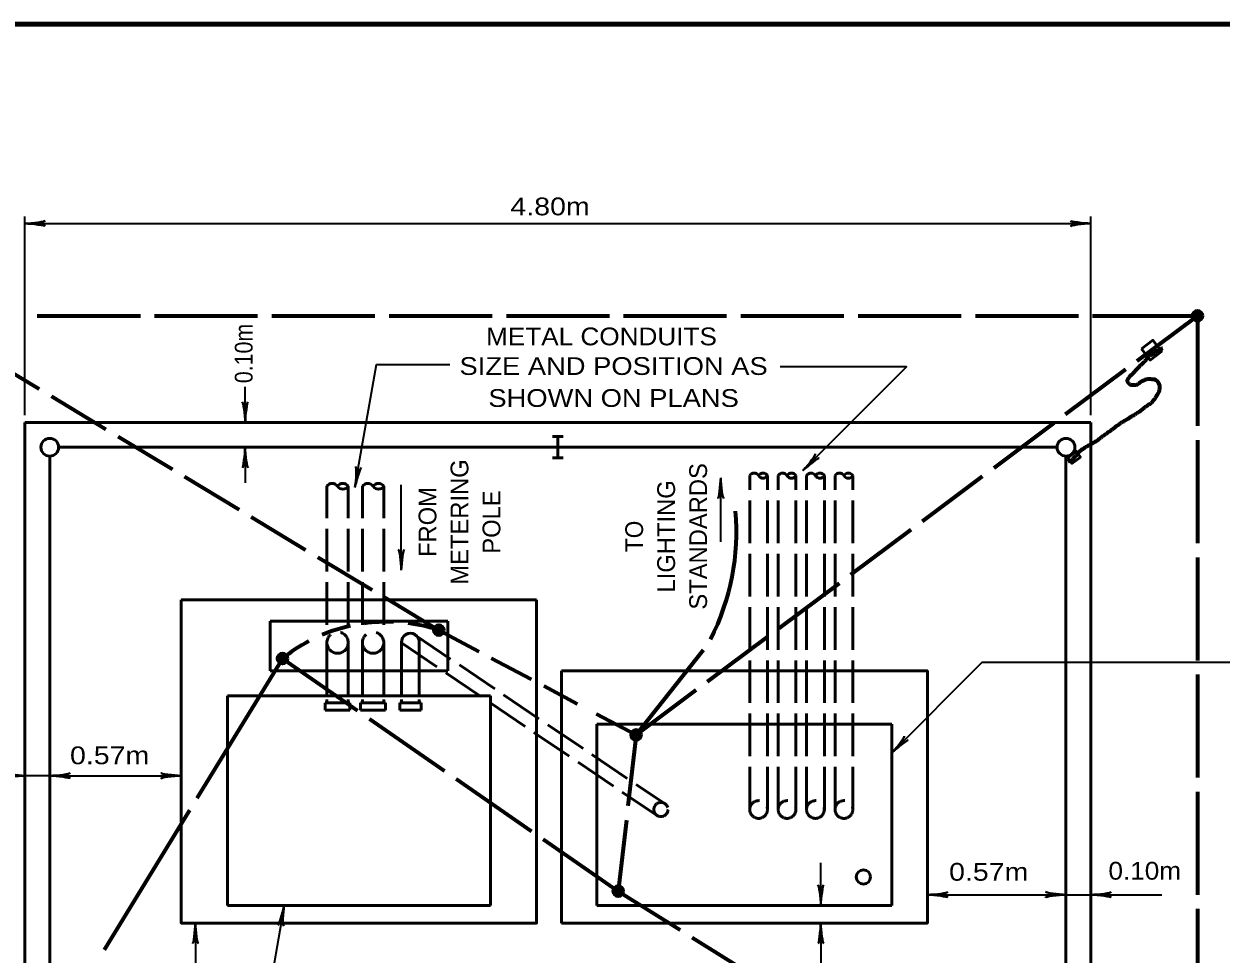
# Model space of a CAD drawing. Extents: x -30 to 826, y -11 to 533.
# Drawn here: x 133.1 to 335.3, y 369.9 to 527 of the extents above; entities that cross this region are included whole.
import ezdxf
from ezdxf.enums import TextEntityAlignment as Align

# ---------------------------------------------------------------- set-up
doc = ezdxf.new("R2010")
doc.units = 0
doc.header["$LTSCALE"] = 1.2
doc.linetypes.add('LONG_DASHED', pattern=[7.5, 6, -1.5])
doc.layers.add('1', color=7, linetype='Continuous', lineweight=53)

msp = doc.modelspace()

# ---------------------------------------------------------------- hatches: boundary and pattern name
at = {"layer": '1'}
for points in [[(332.199, 477.732, 1), (330.399, 477.732, 1)], [(204.099, 424.632, 1), (202.299, 424.632, 1)], [(177.699, 419.832, 1), (175.899, 419.832, 1)], [(237.399, 406.932, 1), (235.599, 406.932, 1)], [(234.399, 380.532, 1), (232.599, 380.532, 1)]]:
    msp.add_hatch(color=256, dxfattribs=at).paths.add_polyline_path(points)

# ---------------------------------------------------------------- linework, layer by layer
at = {"layer": '1', "lineweight": 35}
for p, q in [((133.299, 460.932), (133.299, 494.532)), ((133.299, 493.332), (313.299, 493.332)), ((313.299, 460.932), (313.299, 494.532)), ((170.499, 459.732), (170.499, 465.732)), ((170.499, 455.532), (170.499, 449.532)), ((196.859, 434.795), (196.859, 449.195)), ((250.808, 439.55), (250.808, 450.35)), ((133.299, 400.032), (121.299, 400.032)), ((137.499, 400.032), (133.299, 400.032)), ((137.499, 400.032), (159.699, 400.032)), ((267.699, 378.132), (267.699, 385.332)), ((162.099, 375.132), (162.099, 344.532)), ((267.699, 375.132), (267.699, 364.332))]:
    msp.add_line(p, q, dxfattribs=at)
at = {"layer": '1', "lineweight": 70}
for p, q in [((135.399, 477.732), (152.799, 477.732)), ((155.199, 477.732), (172.599, 477.732)), ((174.999, 477.732), (192.399, 477.732)), ((194.799, 477.732), (212.199, 477.732)), ((214.599, 477.732), (231.999, 477.732)), ((234.399, 477.732), (251.799, 477.732)), ((254.199, 477.732), (271.599, 477.732)), ((273.999, 477.732), (291.399, 477.732)), ((293.799, 477.732), (311.199, 477.732)), ((313.599, 477.732), (331.299, 477.732)), ((321.131, 470.139), (331.299, 477.732)), ((331.299, 477.732), (331.299, 459.132)), ((126.543, 470.94), (135.733, 465.388)), ((309.041, 461.109), (319.208, 468.703)), ((137.787, 464.147), (146.977, 458.595)), ((296.951, 452.08), (307.118, 459.673)), ((149.031, 457.354), (158.222, 451.803)), ((331.299, 456.732), (331.299, 439.332)), ((160.276, 450.562), (169.466, 445.01)), ((284.86, 443.05), (295.028, 450.644)), ((171.52, 443.769), (180.71, 438.218)), ((272.77, 434.021), (282.937, 441.614)), ((182.764, 436.977), (191.954, 431.425)), ((331.299, 436.932), (331.299, 419.532)), ((260.68, 424.991), (270.847, 432.585)), ((194.009, 430.184), (203.199, 424.632)), ((203.199, 424.632), (209.934, 421.052)), ((248.589, 415.962), (258.757, 423.555)), ((236.499, 406.932), (247.899, 421.332)), ((176.799, 419.832), (162.363, 396.243)), ((176.799, 419.832), (189.494, 411.033)), ((212.054, 419.926), (218.789, 416.346)), ((331.299, 417.132), (331.299, 399.732)), ((220.908, 415.219), (226.584, 412.202)), ((236.499, 406.932), (246.666, 414.526)), ((229.763, 410.512), (236.499, 406.932)), ((191.467, 409.665), (204.163, 400.866)), ((236.499, 406.932), (235.134, 394.925)), ((206.135, 399.499), (218.831, 390.699)), ((331.299, 397.332), (331.299, 379.932)), ((161.111, 394.196), (146.675, 370.606)), ((234.863, 392.54), (233.499, 380.532)), ((220.803, 389.332), (233.499, 380.532)), ((233.499, 380.532), (243.944, 373.996)), ((331.299, 377.532), (331.299, 360.132)), ((245.978, 372.723), (256.423, 366.187))]:
    msp.add_line(p, q, dxfattribs=at)
at = {"layer": '1'}
for p, q in [((133.299, 459.732), (313.299, 459.732)), ((133.299, 459.732), (133.299, 338.532)), ((313.299, 459.732), (313.299, 338.532)), ((222.399, 457.332), (224.199, 457.332)), ((223.299, 457.332), (223.299, 453.732)), ((138.999, 455.532), (307.599, 455.532)), ((137.499, 454.032), (137.499, 346.032)), ((222.399, 453.732), (224.199, 453.732)), ((309.099, 454.032), (309.099, 346.032)), ((159.699, 429.732), (219.699, 429.732)), ((174.699, 426.132), (204.699, 426.132)), ((174.699, 426.132), (174.699, 417.732)), ((204.699, 417.732), (204.699, 426.132)), ((184.299, 422.532), (184.299, 413.532)), ((187.899, 422.532), (187.899, 413.532)), ((190.299, 422.532), (190.299, 413.532)), ((193.899, 422.532), (193.899, 413.532)), ((196.899, 422.532), (196.899, 413.532)), ((199.899, 422.532), (199.899, 413.532)), ((174.699, 417.732), (204.699, 417.732)), ((223.899, 375.132), (223.899, 417.732)), ((167.499, 413.532), (211.899, 413.532)), ((167.499, 413.532), (167.499, 378.132)), ((184.299, 412.932), (184.299, 412.332)), ((187.899, 412.932), (187.899, 412.332)), ((190.299, 412.932), (190.299, 412.332)), ((193.899, 412.932), (193.899, 412.332)), ((196.899, 412.932), (196.899, 412.332)), ((199.899, 412.932), (199.899, 412.332)), ((211.899, 378.132), (211.899, 413.532)), ((279.699, 408.732), (229.899, 408.732)), ((229.899, 378.132), (229.899, 408.732)), ((279.699, 378.132), (279.699, 408.732)), ((167.499, 378.132), (211.899, 378.132)), ((229.899, 378.132), (279.699, 378.132))]:
    msp.add_line(p, q, dxfattribs=at)
at = {"layer": '1', "linetype": 'LONG_DASHED'}
for p, q in [((184.299, 425.532), (184.299, 448.932)), ((187.899, 425.532), (187.899, 448.932)), ((190.299, 425.532), (190.299, 448.932)), ((193.899, 425.532), (193.899, 448.932)), ((255.699, 394.332), (255.699, 450.732)), ((258.699, 394.332), (258.699, 450.732)), ((260.499, 394.332), (260.499, 450.732)), ((263.499, 394.332), (263.499, 450.732)), ((265.299, 394.332), (265.299, 450.732)), ((268.299, 394.332), (268.299, 450.732)), ((270.099, 394.332), (270.099, 450.732)), ((273.099, 394.332), (273.099, 450.732)), ((196.899, 422.48), (240.299, 393.139)), ((199.216, 423.786), (241.632, 395.111)), ((183.999, 412.332), (188.199, 412.332)), ((183.999, 412.332), (183.999, 411.132)), ((183.999, 411.132), (188.199, 411.132)), ((188.199, 412.332), (188.199, 411.132)), ((189.999, 412.332), (194.199, 412.332)), ((189.999, 412.332), (189.999, 411.132)), ((189.999, 411.132), (194.199, 411.132)), ((194.199, 412.332), (194.199, 411.132)), ((196.599, 412.332), (200.199, 412.332)), ((196.599, 412.332), (196.599, 411.132)), ((196.599, 411.132), (200.199, 411.132)), ((200.199, 412.332), (200.199, 411.132))]:
    msp.add_line(p, q, dxfattribs=at)
at = {"layer": '1', "lineweight": 158}
msp.add_lwpolyline([(819.196, 527.044), (27.496, 526.944), (27.596, 0.944)], dxfattribs=at)
at = {"layer": '1'}
for points in [[(321.855, 472.177), (323.778, 473.613), (325.214, 471.69), (323.292, 470.254)], [(309.385, 453.753), (310.827, 454.83), (311.545, 453.868), (310.103, 452.791), (309.385, 453.753)]]:
    msp.add_lwpolyline(points, close=True, dxfattribs=at)
at = {"layer": '1', "lineweight": 35}
for points in [[(189.031, 448.766), (192.694, 469.537), (205.038, 469.537)], [(264.675, 451.599), (282.189, 469.113), (260.81, 469.113)], [(279.699, 403.932), (294.972, 419.206), (340.444, 419.206)], [(177.099, 378.132), (175.149, 367.075), (179.094, 367.075)], [(285.699, 379.932), (309.099, 379.932), (313.299, 379.932), (325.299, 379.932)]]:
    msp.add_lwpolyline(points, dxfattribs=at)
at = {"layer": '1'}
for points in [[(159.699, 429.732), (159.699, 375.132), (219.699, 375.132), (219.699, 429.732)], [(223.899, 375.132), (285.699, 375.132), (285.699, 417.732), (223.899, 417.732)]]:
    msp.add_lwpolyline(points, dxfattribs=at)
for centre, radius in [((331.299, 477.732), 0.9), ((137.499, 455.532), 1.5), ((309.099, 455.532), 1.5), ((203.199, 424.632), 0.9), ((176.799, 419.832), 0.9), ((236.499, 406.932), 0.9), ((274.899, 382.932), 1.2), ((233.499, 380.532), 0.9)]:
    msp.add_circle(centre, radius, dxfattribs=at)
at = {"layer": '1', "linetype": 'LONG_DASHED'}
for centre, radius in [((186.099, 422.532), 1.8), ((192.099, 422.532), 1.8), ((240.699, 394.332), 1.2), ((257.199, 394.332), 1.5), ((261.999, 394.332), 1.5), ((266.799, 394.332), 1.5), ((271.599, 394.332), 1.5)]:
    msp.add_circle(centre, radius, dxfattribs=at)
at = {"layer": '1'}
for centre, radius, start, end in [((256.449, 450.307), 0.862, 29.57629, 150.42371), ((257.949, 450.307), 0.862, 29.57629, 150.42371), ((261.249, 450.307), 0.862, 29.57629, 150.42371), ((262.749, 450.307), 0.862, 29.57629, 150.42371), ((266.049, 450.307), 0.862, 29.57629, 150.42371), ((267.549, 450.307), 0.862, 29.57629, 150.42371), ((270.849, 450.307), 0.862, 29.57629, 150.42371), ((272.349, 450.307), 0.862, 29.57629, 150.42371), ((185.199, 448.345), 1.075, 33.11864, 146.88135), ((186.999, 448.345), 1.075, 33.11864, 146.88135), ((186.999, 449.519), 1.075, 213.11865, 326.88136), ((191.199, 448.345), 1.075, 33.11864, 146.88135), ((192.999, 448.345), 1.075, 33.11864, 146.88135), ((192.999, 449.519), 1.075, 213.11865, 326.88136), ((257.949, 451.158), 0.862, 209.57629, 330.42371), ((262.749, 451.158), 0.862, 209.57629, 330.42371), ((267.549, 451.158), 0.862, 209.57629, 330.42371), ((272.349, 451.158), 0.862, 209.57629, 330.42371), ((198.399, 422.61), 1.502, 357.01919, 182.98081)]:
    msp.add_arc(centre, radius, start, end, dxfattribs=at)
at = {"layer": '1', "lineweight": 70}
for centre, radius, start, end in [((213.771, 441.21), 39.685, 332.90084, 5.09207), ((194.421, 397.91), 28.127, 102.75016, 112.84762), ((194.421, 397.91), 28.127, 87.76241, 97.85974), ((194.421, 397.91), 28.127, 71.81547, 82.6976), ((194.421, 397.91), 28.127, 117.91242, 128.79422)]:
    msp.add_arc(centre, radius, start, end, dxfattribs=at)
at = {"layer": '1', "lineweight": 40}
for centre, major_axis, ratio, start_param, end_param in [((134.643, 493.078), (2.108, -0.211), 0.07063, 6.2823074, 8.5597026), ((134.643, 493.078), (2.108, -0.211), 0.07063, 6.2823074, 8.5597026), ((134.608, 493.664), (-2.143, -0.187), 0.122415, 0.8963533, 3.1415927), ((134.608, 493.664), (-2.143, -0.187), 0.122415, 0.8963533, 3.1415927), ((311.989, 493.001), (2.143, 0.187), 0.122415, 0.8963533, 3.1415927), ((311.954, 493.586), (-2.108, 0.211), 0.07063, 6.2823074, 8.5597026), ((170.167, 461.042), (0.187, -2.143), 0.122415, 0.8963533, 3.1415927), ((170.167, 461.042), (0.187, -2.143), 0.122415, 0.8963533, 3.1415927), ((170.753, 461.077), (0.211, 2.108), 0.07063, 6.2823074, 8.5597026), ((170.753, 461.077), (0.211, 2.108), 0.07063, 6.2823074, 8.5597026), ((170.245, 454.188), (-0.211, -2.108), 0.07063, 6.2823074, 8.5597026), ((170.83, 454.223), (-0.187, 2.143), 0.122415, 0.8963533, 3.1415927), ((265.366, 452.759), (-1.383, -1.648), 0.122415, 0.8963533, 3.1415927), ((265.805, 452.37), (1.639, 1.341), 0.07063, 6.2823074, 8.5597026), ((188.932, 450.113), (-0.188, -2.143), 0.122415, 0.8963533, 3.1415927), ((188.932, 450.113), (-0.188, -2.143), 0.122415, 0.8963533, 3.1415927), ((189.515, 450.046), (0.574, 2.039), 0.07063, 6.2823074, 8.5597026), ((189.515, 450.046), (0.574, 2.039), 0.07063, 6.2823074, 8.5597026), ((250.554, 449.005), (0.211, 2.108), 0.07063, 3.1407148, 5.41811), ((250.554, 449.005), (0.211, 2.108), 0.07063, 3.1407148, 5.41811), ((251.139, 449.041), (-0.187, 2.143), 0.122415, 0.8963533, 3.1415927), ((251.139, 449.041), (-0.187, 2.143), 0.122415, 0.8963533, 3.1415927), ((196.528, 436.104), (0.187, -2.143), 0.122415, 0.8963533, 3.1415927), ((196.528, 436.104), (0.187, -2.143), 0.122415, 0.8963533, 3.1415927), ((197.113, 436.14), (-0.211, -2.108), 0.07063, 3.1407148, 5.41811), ((197.113, 436.14), (-0.211, -2.108), 0.07063, 3.1407148, 5.41811), ((280.39, 405.093), (-1.383, -1.648), 0.122415, 0.8963533, 3.1415927), ((280.39, 405.093), (-1.383, -1.648), 0.122415, 0.8963533, 3.1415927), ((280.829, 404.704), (1.639, 1.341), 0.07063, 6.2823074, 8.5597026), ((280.829, 404.704), (1.639, 1.341), 0.07063, 6.2823074, 8.5597026), ((131.954, 400.286), (2.108, -0.211), 0.07063, 3.1407148, 5.41811), ((131.954, 400.286), (2.108, -0.211), 0.07063, 3.1407148, 5.41811), ((138.808, 400.364), (-2.143, -0.187), 0.122415, 0.8963533, 3.1415927), ((138.808, 400.364), (-2.143, -0.187), 0.122415, 0.8963533, 3.1415927), ((158.354, 400.286), (2.108, -0.211), 0.07063, 3.1407148, 5.41811), ((131.989, 399.701), (2.143, 0.187), 0.122415, 0.8963533, 3.1415927), ((131.989, 399.701), (2.143, 0.187), 0.122415, 0.8963533, 3.1415927), ((138.843, 399.778), (-2.108, 0.211), 0.07063, 3.1407148, 5.41811), ((138.843, 399.778), (-2.108, 0.211), 0.07063, 3.1407148, 5.41811), ((158.389, 399.701), (2.143, 0.187), 0.122415, 0.8963533, 3.1415927), ((267.367, 379.442), (0.187, -2.143), 0.122415, 0.8963533, 3.1415927), ((267.367, 379.442), (0.187, -2.143), 0.122415, 0.8963533, 3.1415927), ((267.953, 379.477), (-0.211, -2.108), 0.07063, 3.1407148, 5.41811), ((267.953, 379.477), (-0.211, -2.108), 0.07063, 3.1407148, 5.41811), ((287.008, 380.264), (-2.143, -0.187), 0.122415, 0.8963533, 3.1415927), ((307.754, 380.186), (2.108, -0.211), 0.07063, 3.1407148, 5.41811), ((307.754, 380.186), (2.108, -0.211), 0.07063, 3.1407148, 5.41811), ((314.608, 380.264), (-2.143, -0.187), 0.122415, 0.8963533, 3.1415927), ((176.615, 376.852), (-0.574, -2.039), 0.07063, 6.2823074, 8.5597026), ((177.198, 376.785), (0.188, 2.143), 0.122415, 0.8963533, 3.1415927), ((287.043, 379.678), (-2.108, 0.211), 0.07063, 3.1407148, 5.41811), ((307.789, 379.601), (2.143, 0.187), 0.122415, 0.8963533, 3.1415927), ((307.789, 379.601), (2.143, 0.187), 0.122415, 0.8963533, 3.1415927), ((314.643, 379.678), (-2.108, 0.211), 0.07063, 3.1407148, 5.41811), ((161.845, 373.788), (0.211, 2.108), 0.07063, 3.1407148, 5.41811), ((161.845, 373.788), (0.211, 2.108), 0.07063, 3.1407148, 5.41811), ((162.43, 373.823), (-0.187, 2.143), 0.122415, 0.8963533, 3.1415927), ((162.43, 373.823), (-0.187, 2.143), 0.122415, 0.8963533, 3.1415927), ((267.445, 373.788), (0.211, 2.108), 0.07063, 3.1407148, 5.41811), ((268.03, 373.823), (-0.187, 2.143), 0.122415, 0.8963533, 3.1415927)]:
    msp.add_ellipse(centre, major_axis=major_axis, ratio=ratio, start_param=start_param, end_param=end_param, dxfattribs=at)
at = {"layer": '1', "lineweight": 70}
for points in [[(322.125, 466.75), (321.875, 466.625), (321.656, 466.5), (321.468, 466.375), (321.312, 466.218), (321.093, 466.093), (320.843, 466.031), (320.593, 465.999), (320.312, 465.999), (319.999, 466.093), (319.78, 466.25), (319.624, 466.437), (319.499, 466.625), (319.499, 466.938), (319.686, 467.282), (319.874, 467.501), (319.999, 467.657), (320.249, 467.845), (320.374, 468.001), (320.624, 468.22), (320.781, 468.439), (320.999, 468.658), (321.218, 468.877), (321.406, 469.065), (321.625, 469.315), (321.844, 469.502), (322, 469.659), (322.25, 469.878), (322.438, 470.066), (322.625, 470.316), (322.75, 470.503), (322.875, 470.66), (323.094, 470.91), (323.313, 471.066), (323.594, 471.192), (323.813, 471.317), (324.095, 471.536), (324.345, 471.755), (324.657, 471.88), (324.939, 471.974), (325.158, 472.099), (325.345, 472.255), (325.408, 472.286)], [(321.376, 461.441), (321.505, 461.545), (321.755, 461.732), (321.943, 461.889), (322.131, 462.045), (322.35, 462.233), (322.6, 462.42), (322.787, 462.546), (323.006, 462.702), (323.319, 462.89), (323.506, 463.015), (323.631, 463.171), (323.756, 463.328), (323.944, 463.547), (324.1, 463.734), (324.225, 463.891), (324.444, 464.235), (324.569, 464.485), (324.726, 464.735), (324.819, 464.954), (324.913, 465.236), (324.944, 465.517), (324.944, 465.767), (324.913, 466.049), (324.788, 466.362), (324.569, 466.674), (324.319, 466.831), (324.132, 466.956), (323.85, 466.987), (323.475, 467.018), (323.037, 467.018), (322.756, 466.987)], [(322.756, 466.987), (322.475, 466.925), (322.287, 466.831), (322.037, 466.706), (321.944, 466.647)], [(309.463, 453.112), (309.744, 453.238), (309.994, 453.363), (310.182, 453.488), (310.338, 453.644), (310.557, 453.863), (310.745, 454.051), (310.87, 454.207), (311.026, 454.426), (311.214, 454.645), (311.433, 454.864), (311.651, 455.02), (311.839, 455.208), (312.151, 455.364), (312.308, 455.49), (312.495, 455.615), (312.683, 455.709), (312.996, 455.896), (313.34, 456.053), (313.652, 456.24), (313.871, 456.397), (314.184, 456.584), (314.559, 456.803), (314.872, 457.054), (315.247, 457.335), (315.559, 457.554), (315.716, 457.679), (315.903, 457.804), (316.153, 458.023), (316.31, 458.148), (316.529, 458.242), (316.779, 458.461), (316.966, 458.586), (317.185, 458.743), (317.341, 458.868), (317.529, 459.055), (317.717, 459.18), (317.998, 459.368), (318.186, 459.493), (318.405, 459.681), (318.655, 459.806), (318.905, 459.962), (319.217, 460.15), (319.468, 460.307), (319.749, 460.463), (319.968, 460.651), (320.249, 460.807), (320.562, 460.963), (320.781, 461.089), (320.999, 461.214), (321.25, 461.401), (321.468, 461.526), (321.656, 461.651), (321.743, 461.709)]]:
    msp.add_spline(points, degree=3, dxfattribs=at)

# ---------------------------------------------------------------- texts
at = {"layer": '1'}
for s, width, p in [('4.80m', 1.2, (215.29, 494.713)), ('METAL CONDUITS', 1.1, (211.174, 472.754)), ('0.57m', 1.2, (140.921, 401.98)), ('0.57m', 1.2, (289.36, 382.303)), ('0.10m', 1.1, (316.267, 382.482))]:
    msp.add_text(s, height=3, dxfattribs=dict(at, width=width)).set_placement(p)
at = {"layer": '1', "width": 0.9}
msp.add_text('0.10m', height=3, rotation=90, dxfattribs=at).set_placement((171.749, 466.352))
at = {"layer": '1', "width": 1.15}
for s, p in [('SIZE AND POSITION AS', (232.713, 467.747)), ('SHOWN ON PLANS', (232.713, 462.347))]:
    msp.add_text(s, height=3, dxfattribs=at).set_placement(p, align=Align.CENTER)
at = {"layer": '1'}
for s, p in [('METERING', (208.189, 442.899)), ('STANDARDS', (248.487, 440.473)), ('LIGHTING', (243.087, 440.473)), ('FROM', (202.789, 442.899)), ('POLE', (213.589, 442.899))]:
    msp.add_text(s, height=3, rotation=90, dxfattribs=at).set_placement(p, align=Align.CENTER)
at = {"layer": '1', "width": 0.95}
msp.add_text('TO', height=3, rotation=90, dxfattribs=at).set_placement((237.687, 440.473), align=Align.CENTER)

doc.saveas('drawing.dxf')
